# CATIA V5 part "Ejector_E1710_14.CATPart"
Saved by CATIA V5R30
Part number: Vyhazovac_4x160_2
Nomenclature: E1710/4x160
Description: MEUSBURGER
Property "Material": "1.221"
Publications: "__DrillHole", "Base"
Bounding box of the stored display mesh (mm): x -3.996 to 3.996, y -3.999 to 3.999, z 0 to 152
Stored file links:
  E:\Bakalarka\Model\Forma_v7\Ejector_E1710_14.CATPart
  E:\dev\MoldDesign\intel_a\startup\components\MoldCatalog\Ejector\Meusburger\Ejector_E1710\TableE1710.txt
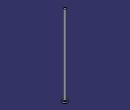
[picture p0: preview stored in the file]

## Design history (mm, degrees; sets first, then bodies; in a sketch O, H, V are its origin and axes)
Parameters
  Ref = "E1710/4x160" {design table}
  D1 = 4 mm {design table}
  D3 = 8 mm {design table}
  L = 160 mm {design table}
  L3 = 3 mm {design table}
  R = 0.3 mm {design table}
  k_d3 = 9 mm {design table}
  k_d1 = 4.2 mm {design table}
  k_F = 0.3 mm {design table}
  kl = 17 mm {design table}
  Mat = "1.221" {design table}
  HeatTreat = "ISO6751" {design table}
  Offset_Parting = 10 mm
  Anti_Rotation = "Normal"
  Anti_Rotation_D = 2.3 mm
  Anti_Rotation_D_Icut = 2.3 mm
  Add_Length_L = 0.8377 mm
  Add_Length_D3 = 0 mm
  SupplierRef = "Meusburger 2017"
  BmpRef = "F_MldEjectorD1"
  DrillHole_Length = 225 mm
  ValidationTest = false
  Anti_Rotation_D_min = 2.3 mm {= OffSet_D1 /2}
  Anti_Rotation_D_max = 3.925 mm {= D3/2-0.075mm}
  Anti_Rotation_D_ref = 2.3 mm {= Anti_Rotation_D}
  Anti_Rotation_D_Icut_ref = 2.3 mm {= Anti_Rotation_D_Icut}
  Anti_Rotation_Ref_Icut = 2.3246 mm
  Offset_L = 20 mm
  D = 4 mm {= D1}
  OffSet_D1 = 4.6 mm {= D1+2*R}
  OffSet_D3 = 9 mm {= D3+1mm}
  XG_Split = -66.5 mm
  YG_Split = 54.5 mm
  ZG_Split = -198 mm
  DirX_Split = 0 mm
  DirY_Split = 0 mm
  DirZ_Split = 1 mm
Set1 "BaseBody"
  Point1 "Base": (0, 0, 0)
  Plane1: type Offset, RefPlane xy-plane, Offset 225 {= DrillHole_Length}, reversed
  Sketch1 "Sketch.2" on xy-plane, origin (0, 0, 0), H (1, 0, 0), V (0, 1, 0)
    point P1 (-0.46, 1.1623)
    point P2 (0.46, 1.1623)
    construction line L1 (-0.46, 1.1623) -> (0.46, 1.1623)
    point P3 (0.46, -1.1623)
    line L2 (0.46, -1.1623) -> (0.46, 1.1623)
    point P4 (-0.46, -1.1623)
    construction line L3 (0.46, -1.1623) -> (-0.46, -1.1623)
    line L4 (-0.46, 1.1623) -> (-0.46, -1.1623)
    point P5 (-0.21, 1.1623)
    arc A1 centre (-0.21, 1.1623) radius 0.25 from (-0.21, 1.4123) to (-0.46, 1.1623) ccw
    point P7 (0.21, 1.1623)
    point P8 (0.21, 1.4123)
    arc A2 centre (0.21, 1.1623) radius 0.25 from (0.46, 1.1623) to (0.21, 1.4123) ccw
    line L5 (-0.21, 1.4123) -> (0.21, 1.4123)
    point P9 (-0.46, -1.1623)
    arc A3 centre (-0.21, -1.1623) radius 0.25 from (-0.46, -1.1623) to (-0.21, -1.4123) ccw
    point P11 (0.21, -1.4123)
    line L6 (-0.21, -1.4123) -> (0.21, -1.4123)
    point P12 (0.46, -1.1623)
    arc A4 centre (0.21, -1.1623) radius 0.25 from (0.21, -1.4123) to (0.46, -1.1623) ccw
    point P14 (-0.46, 1.1623)
    point P15 (-0.46, -1.1623)
    point P16 (0.46, 1.1623)
    point P17 (0.46, -1.1623)
    reference projected circle E1 centre (0, 0) radius 1.25 from edge [face of Shaft1 from Sketch2.L3 | face of Shaft1 from Sketch2.L4]
    reference projected circle E2 centre (0, 0) radius 1.25 from edge [face of Shaft1 from Sketch2.L3 | face of Shaft1 from Sketch2.L4]
    reference projected circle E3 centre (0, 0) radius 1.25 from edge [face of Shaft1 from Sketch2.L3 | face of Shaft1 from Sketch2.L4]
    reference projected circle E4 centre (0, 0) radius 1.25 from edge [face of Shaft1 from Sketch2.L3 | face of Shaft1 from Sketch2.L4]
    point P18 (-0.46, -1.1623)
    point P19 (-0.21, -1.4123)
    point P20 (0.21, -1.4123)
    point P21 (0.46, -1.1623)
    point P22 (-0.21, -1.4123)
    point P23 (0.21, -1.4123)
    distance P14 P15 = 2.3246 (reference)
    distance P16 P17 = 2.3246 (reference)
    distance L1 P14 = 0 (reference)
    radius A1 = 2
    distance L4 V = 2.31
    distance L2 V = 3.935
    distance L5 L6 = 8
    horizontal: L1 H, L3 H, L5 H
    vertical: L2 V, L4 V
    coincidence: P5 L1, P7 L1, P3 P12, P14 L4, P15 L4, P16 L2, P17 L2, P14 E1, P15 E2, P16 E3, P17 E4, P3 P21, P4 P18, P20 P23, P19 P22
    tangency: A1 L4, A2 L2, A2 L5, A1 L5
    symmetry: P1 P9 H, A1 A3 H, P8 P11 H, L5 L6 H, P2 P12 H, A2 A4 H
  DatumSurface1
Body1 "PartBody" (main body)
  Sketch2 "Sketch.1" on zx-plane, origin (0, 0, 0), H (-1, 0, 0), V (0, 0, 1)
    point P1 (0, 160)
    line L1 (2, 160) -> (0, 160)
    line L2 (2, 3) -> (2, 160)
    line L3 (4, 3) -> (2, 3)
    line L4 (4, 0) -> (4, 3)
    point P5 (0, 0)
    line L5 (0, 0) -> (4, 0)
    point P6 (0, 160)
    axis line L6 (0, 160) -> (0, 0)
    point P7 (0, 0)
    point P8 (2, 3)
    point P9 (2, 3)
    line L7 (0, 160) -> (0, 0)
    distance L5 L3 = 3 {= L3}
    distance L5 L1 = 160 {= L}
    distance L2 L6 = 2 {= D1 /2}
    distance L4 L6 = 4 {= D3 /2}
    coincidence: L6 P5, P1 L6, L5 H, L6 V, P7 O, P6 P1, P8 P9
    vertical: L2 V, L7 V
    horizontal: L1 H
  Shaft1 "Shaft.1": profile Sketch2, axis Sketch2.L6, angle 360
  Pocket1 "Pocket.1": profile Sketch1, direction (0, 0, 1), length 4, outer side, deactivated
  Pocket2 "Pocket.2": profile Sketch1, direction (0, 0, 1), length 4, outer side, deactivated
  Fillet1: radius 0.3 {= R}, on edge [face of Shaft1 from Sketch2.L2 | face of Shaft1 from Sketch2.L3]
  Pocket3: profile face of Shaft1 from Sketch2.L1, direction along face of Shaft1 from Sketch2.L1 reversed, up to face of DatumSurface1
Body2 "__DrillHole"
  Sketch3 "Sketch.3" on face of Shaft1, origin (0, 0, 0), H (1, 0, 0), V (0, -1, 0)
    point P1 (0, 0)
    reference projected point E1 (0, 0) from Point1
    coincidence: E1 P1
  Hole1 "Hole.1": placed by Sketch3, at (0, 0, 0) direction (0, 0, 1), diameter 4.6 {= OffSet_D1}, depth 140 {= L-Offset_L}
  Sketch4 "Sketch.4" on face of Shaft1, origin (0, 0, 0), H (1, 0, 0), V (0, -1, 0)
    point P1 (0, 0)
    reference projected point E1 (0, 0) from Point1
    coincidence: E1 P1
  Hole2 "Hole.2": placed by Sketch4, at (0, 0, 0) direction (0, 0, 1), diameter 4 {= D1}, depth 160 {= L}
  Sketch5 "Sketch.5" on face of Shaft1 from Sketch2.L3, origin (0, 0, 3), H (1, 0, 0), V (0, 1, 0)
    point P1 (0, 0)
    reference projected point E1 (0, 0) from Point1
    coincidence: E1 P1
  Hole3 "Hole.3": placed by Sketch5, at (0, 0, 3) direction (0, 0, -1), diameter 9 {= OffSet_D3}, depth 228 {= L3 +DrillHole_Length}
  Chamfer1: length 0.3 {= k_F}, angle 45, on edge [face of Hole1 | face of Hole3]
  Body3 "__Body.1"
    Pocket4 "Pocket.3": profile Sketch1, direction (0, 0, -1), length 225, opposite side length 3, deactivated
  Assemble1: tool Body3
  Chamfer2: length 0.3 {= k_F}, angle 45, on edge [start face of Pocket4 | face of Hole1], deactivated
  Body4 "__Body.2"
    Pocket5 "Pocket.4": profile Sketch1, direction (0, 0, -1), length 225, opposite side length 3, deactivated
  Assemble2: tool Body4
  Chamfer3: length 0.3 {= k_F}, angle 45, on edge [start face of Pocket5 | face of Hole1], deactivated
Relations
  design table "TableE1710", configuration 187, drives Ref, D1, D3, L, L3, R, k_d3, k_d1, k_F, kl, Mat, HeatTreat
  Offset_L = 20mm (deactivated)
  rule "Cut_Head_rule":
    let sketch_cut (length)
    let PartBody_Pocket_Sketch (Boolean)
    let I_PartBody_Pocket (Boolean)
    let D_PartBody_Pocket (Boolean)
    let N_DrillHole_Hole (Boolean)
    let N_DrillHole_Hole_Sketch (Boolean)
    let I_DrillHole_Pocket (Boolean)
    let D_DrillHole_Pocket (Boolean)
    /* --------------------------------------------------------------------------------------*/
    if Anti_Rotation =="Normal"
    {
    	sketch_cut=Anti_Rotation_D_max
    	PartBody_Pocket_Sketch = false
    	I_PartBody_Pocket = false
    	D_PartBody_Pocket = false
    	N_DrillHole_Hole = true
    	N_DrillHole_Hole_Sketch = true
    	I_DrillHole_Pocket = false
    	D_DrillHole_Pocket = false
    	Chamfer1.Activity= true
    	Chamfer2.Activity= false
    	Chamfer3.Activity= false
    }
    if Anti_Rotation == "I_Cut"
    {
    	sketch_cut=Anti_Rotation_D_Icut_ref
    	PartBody_Pocket_Sketch = true
    	I_PartBody_Pocket = true
    	D_PartBody_Pocket = false
    	N_DrillHole_Hole = false
    	N_DrillHole_Hole_Sketch = false
    	I_DrillHole_Pocket = true
    	D_DrillHole_Pocket = false
    	Chamfer1.Activity= false
    	Chamfer2.Activity= true
    	Chamfer3.Activity= false
    }
    if Anti_Rotation =="D_Cut"
    {
    	sketch_cut=Anti_Rotation_D_max
    	PartBody_Pocket_Sketch = true
    	I_PartBody_Pocket = false
    	D_PartBody_Pocket = true
    	N_DrillHole_Hole = false
    	N_DrillHole_Hole_Sketch = false
    	I_DrillHole_Pocket = false
    	D_DrillHole_Pocket = true
    	Chamfer1.Activity= false
    	Chamfer2.Activity= false
    	Chamfer3.Activity= true
    }
    /* --------------------------------------------------------------------------------------*/
    Sketch1.distance(L2 V) = sketch_cut+0.01mm
    Sketch1.distance(L4 V) =Anti_Rotation_D_ref+0.01mm
    Sketch1.radius(A1) =D/2
    Pocket4.FirstLimit.Depth = DrillHole_Length
    Pocket5.FirstLimit.Depth = DrillHole_Length
    Pocket1.FirstLimit.Depth = L3+1mm
    Pocket2.FirstLimit.Depth = L3+1mm
    Pocket4.SecondLimit.Depth = L3
    Pocket5.SecondLimit.Depth =L3
    Pocket1.Activity = I_PartBody_Pocket
    Pocket2.Activity = D_PartBody_Pocket
    Sketch1.Activity =PartBody_Pocket_Sketch
    Hole3.Activity= N_DrillHole_Hole
    Sketch5.Activity = N_DrillHole_Hole_Sketch
    Pocket4.Activity = I_DrillHole_Pocket
    Pocket5.Activity  = D_DrillHole_Pocket
  rule "Anti_Rotation_Icut_constrain":
    let Ref1(length)
    let Ref2(length)
    let Ref3(length)
    let Diam1(length)
    let Diam2(length)
    let Add_Length_Lmin (length)
    Ref1=Sketch1.distance(P14 P15)
    Ref2=Sketch1.distance(P16 P17)
    Diam1=D
    Diam2=D3
    /* --------------------------------------------------------------------*/
    if Ref1 >Ref2
    	Anti_Rotation_Ref_Icut = Ref1
    else
    	Anti_Rotation_Ref_Icut  =Ref2
    Add_Length_D3 .InferiorRange=Anti_Rotation_Ref_Icut /2+Diam1/2 -Diam2/2
    if Add_Length_D3 .InferiorRange<0mm
    	Add_Length_D3 .InferiorRange=0mm
    if ValidationTest == "true"
    	Ref3   = 2*Add_Length_L +Anti_Rotation_Ref_Icut  +2*Diam1/2
    else
    	Ref3  =Diam2+2*Add_Length_D3
    if Ref3 <Diam2
    {
    	Ref3 =Diam2
    }
    /* --------------------------------------------------------------------*/
    Sketch1.distance(L5 L6) = Ref3
    Add_Length_L .InferiorRange=Diam2/2-Anti_Rotation_Ref_Icut/2-Diam1/2
    Add_Length_Lmin=Diam2/2-Anti_Rotation_Ref_Icut/2-Diam1/2
    if Add_Length_Lmin<0mm
    	Add_Length_L .InferiorRange=0mm
    else
    	Add_Length_L .InferiorRange=Add_Length_Lmin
